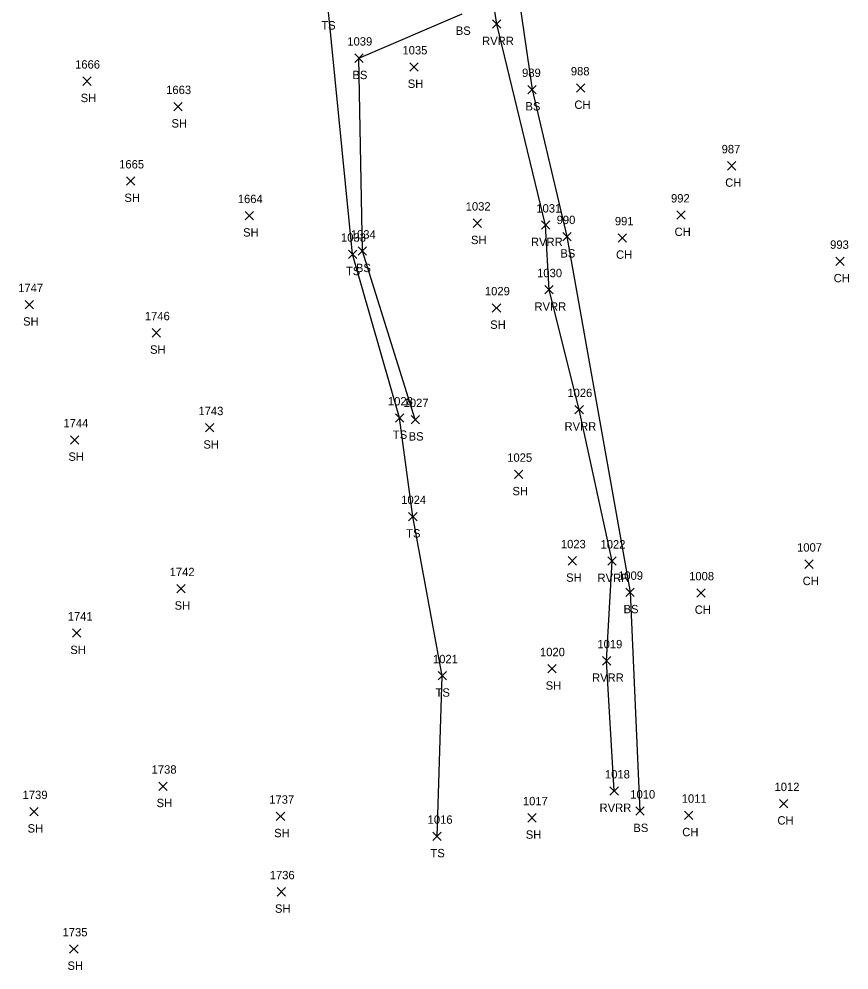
# Model space of a CAD drawing. Extents: x 1885914 to 1887218, y 756253 to 760620.
# Drawn here: x 1886537.5 to 1886735.6, y 759347 to 759574 of the extents above; entities that cross this region are included whole.
import ezdxf

# ---------------------------------------------------------------- set-up
doc = ezdxf.new("R2010")
doc.units = 0
for name, color, linetype in [('L_A', 7, 'Continuous'), ('L_I', 7, 'Continuous'), ('L_TIC', 7, 'Continuous'), ('LAWE', 7, 'Continuous'), ('LELB', 7, 'Continuous')]:
    doc.layers.add(name, color=color, linetype=linetype)

msp = doc.modelspace()

# ---------------------------------------------------------------- linework, layer by layer
at = {"layer": 'L_TIC'}
for points in [[(1886650.51, 759571.8), (1886652.51, 759573.8)], [(1886652.51, 759571.8), (1886650.51, 759573.8)], [(1886617.63, 759563.67), (1886619.63, 759565.67)], [(1886619.63, 759563.67), (1886617.63, 759565.67)], [(1886630.79, 759561.57), (1886632.79, 759563.57)], [(1886632.79, 759561.57), (1886630.79, 759563.57)], [(1886552.71, 759558.18), (1886554.71, 759560.18)], [(1886554.71, 759558.18), (1886552.71, 759560.18)], [(1886658.93, 759556.18), (1886660.93, 759558.18)], [(1886660.93, 759556.18), (1886658.93, 759558.18)], [(1886670.56, 759556.56), (1886672.56, 759558.56)], [(1886672.56, 759556.56), (1886670.56, 759558.56)], [(1886574.4, 759552.1), (1886576.4, 759554.1)], [(1886576.4, 759552.1), (1886574.4, 759554.1)], [(1886706.56, 759537.97), (1886708.56, 759539.97)], [(1886708.56, 759537.97), (1886706.56, 759539.97)], [(1886563.16, 759534.34), (1886565.16, 759536.34)], [(1886565.16, 759534.34), (1886563.16, 759536.34)], [(1886591.49, 759526.07), (1886593.49, 759528.07)], [(1886593.49, 759526.07), (1886591.49, 759528.07)], [(1886694.48, 759526.22), (1886696.48, 759528.22)], [(1886696.48, 759526.22), (1886694.48, 759528.22)], [(1886645.87, 759524.28), (1886647.87, 759526.28)], [(1886647.87, 759524.28), (1886645.87, 759526.28)], [(1886662.16, 759523.82), (1886664.16, 759525.82)], [(1886664.16, 759523.82), (1886662.16, 759525.82)], [(1886667.26, 759521.06), (1886669.26, 759523.06)], [(1886669.26, 759521.06), (1886667.26, 759523.06)], [(1886680.51, 759520.77), (1886682.51, 759522.77)], [(1886682.51, 759520.77), (1886680.51, 759522.77)], [(1886616.11, 759516.86), (1886618.11, 759518.86)], [(1886618.11, 759516.86), (1886616.11, 759518.86)], [(1886618.46, 759517.6), (1886620.46, 759519.6)], [(1886620.46, 759517.6), (1886618.46, 759519.6)], [(1886732.46, 759515.16), (1886734.46, 759517.16)], [(1886734.46, 759515.16), (1886732.46, 759517.16)], [(1886663, 759508.38), (1886665, 759510.38)], [(1886665, 759508.38), (1886663, 759510.38)], [(1886538.98, 759504.82), (1886540.98, 759506.82)], [(1886540.98, 759504.82), (1886538.98, 759506.82)], [(1886650.46, 759504.05), (1886652.46, 759506.05)], [(1886652.46, 759504.05), (1886650.46, 759506.05)], [(1886569.27, 759498.1), (1886571.27, 759500.1)], [(1886571.27, 759498.1), (1886569.27, 759500.1)], [(1886627.32, 759477.77), (1886629.32, 759479.77)], [(1886629.32, 759477.77), (1886627.32, 759479.77)], [(1886670.19, 759479.76), (1886672.19, 759481.76)], [(1886672.19, 759479.76), (1886670.19, 759481.76)], [(1886631.05, 759477.37), (1886633.05, 759479.37)], [(1886633.05, 759477.37), (1886631.05, 759479.37)], [(1886582, 759475.44), (1886584, 759477.44)], [(1886584, 759475.44), (1886582, 759477.44)], [(1886549.78, 759472.54), (1886551.78, 759474.54)], [(1886551.78, 759472.54), (1886549.78, 759474.54)], [(1886655.78, 759464.31), (1886657.78, 759466.31)], [(1886657.78, 759464.31), (1886655.78, 759466.31)], [(1886630.48, 759454.22), (1886632.48, 759456.22)], [(1886632.48, 759454.22), (1886630.48, 759456.22)], [(1886668.59, 759443.66), (1886670.59, 759445.66)], [(1886670.59, 759443.66), (1886668.59, 759445.66)], [(1886678.05, 759443.6), (1886680.05, 759445.6)], [(1886680.05, 759443.6), (1886678.05, 759445.6)], [(1886725.05, 759442.86), (1886727.05, 759444.86)], [(1886727.05, 759442.86), (1886725.05, 759444.86)], [(1886575.13, 759437), (1886577.13, 759439)], [(1886577.13, 759437), (1886575.13, 759439)], [(1886682.34, 759436.14), (1886684.34, 759438.14)], [(1886684.34, 759436.14), (1886682.34, 759438.14)], [(1886699.3, 759436), (1886701.3, 759438)], [(1886701.3, 759436), (1886699.3, 759438)], [(1886550.23, 759426.41), (1886552.23, 759428.41)], [(1886552.23, 759426.41), (1886550.23, 759428.41)], [(1886676.75, 759419.78), (1886678.75, 759421.78)], [(1886678.75, 759419.78), (1886676.75, 759421.78)], [(1886663.7, 759417.89), (1886665.7, 759419.89)], [(1886665.7, 759417.89), (1886663.7, 759419.89)], [(1886637.5, 759416.22), (1886639.5, 759418.22)], [(1886639.5, 759416.22), (1886637.5, 759418.22)], [(1886570.83, 759389.85), (1886572.83, 759391.85)], [(1886572.83, 759389.85), (1886570.83, 759391.85)], [(1886678.54, 759388.71), (1886680.54, 759390.71)], [(1886680.54, 759388.71), (1886678.54, 759390.71)], [(1886719.02, 759385.69), (1886721.02, 759387.69)], [(1886721.02, 759385.69), (1886719.02, 759387.69)], [(1886540.04, 759383.78), (1886542.04, 759385.78)], [(1886542.04, 759383.78), (1886540.04, 759385.78)], [(1886598.9, 759382.67), (1886600.9, 759384.67)], [(1886600.9, 759382.67), (1886598.9, 759384.67)], [(1886684.68, 759383.91), (1886686.68, 759385.91)], [(1886686.68, 759383.91), (1886684.68, 759385.91)], [(1886696.3, 759382.9), (1886698.3, 759384.9)], [(1886698.3, 759382.9), (1886696.3, 759384.9)], [(1886658.95, 759382.3), (1886660.95, 759384.3)], [(1886660.95, 759382.3), (1886658.95, 759384.3)], [(1886636.28, 759377.88), (1886638.28, 759379.88)], [(1886638.28, 759377.88), (1886636.28, 759379.88)], [(1886599.08, 759364.63), (1886601.08, 759366.63)], [(1886601.08, 759364.63), (1886599.08, 759366.63)], [(1886549.57, 759351), (1886551.57, 759353)], [(1886551.57, 759351), (1886549.57, 759353)]]:
    msp.add_lwpolyline(points, dxfattribs=at)
at = {"layer": 'LAWE'}
msp.add_lwpolyline([(1886679.54, 759389.71), (1886677.75, 759420.78), (1886679.05, 759444.6), (1886671.19, 759480.76), (1886664, 759509.38), (1886663.16, 759524.82), (1886651.51, 759572.8), (1886647.18, 759601.26), (1886641.69, 759620.32)], dxfattribs=at)
at = {"layer": 'LELB'}
for points in [[(1886651.59, 759963.58), (1886647.85, 759929.2), (1886639.89, 759913.67), (1886633.14, 759883.1), (1886633.96, 759851.09), (1886632.16, 759822.61), (1886631.66, 759800.6), (1886631.69, 759739.71), (1886631.53, 759709.44), (1886635.98, 759687.07), (1886641.47, 759657.6), (1886645.02, 759644.27), (1886643.52, 759637.8), (1886640.86, 759635.28), (1886641.28, 759631.71), (1886642.18, 759628.94), (1886648.32, 759617.92), (1886654.14, 759597.23), (1886659.93, 759557.18), (1886668.26, 759522.06), (1886683.34, 759437.14), (1886685.68, 759384.91)], [(1886637.28, 759378.88), (1886638.5, 759417.22), (1886631.48, 759455.22), (1886628.32, 759478.77), (1886617.11, 759517.86), (1886611.24, 759576.51), (1886639.28, 759593.88)], [(1886632.05, 759478.37), (1886619.46, 759518.6), (1886618.63, 759564.67), (1886643.3, 759575.24)]]:
    msp.add_lwpolyline(points, dxfattribs=at)

# ---------------------------------------------------------------- texts
at = {"layer": 'L_A'}
for s, p in [('TS', (1886609.65, 759571.51)), ('TS', (1886609.65, 759571.51)), ('BS', (1886641.74, 759570.24)), ('RVRR', (1886648.02, 759567.8)), ('BS', (1886617.07, 759559.67)), ('SH', (1886630.27, 759557.57)), ('SH', (1886552.2, 759554.18)), ('BS', (1886658.37, 759552.18)), ('CH', (1886670.05, 759552.56)), ('SH', (1886573.88, 759548.1)), ('CH', (1886706.05, 759533.97)), ('SH', (1886562.65, 759530.34)), ('SH', (1886590.97, 759522.07)), ('CH', (1886693.96, 759522.22)), ('SH', (1886645.36, 759520.28)), ('RVRR', (1886659.68, 759519.82)), ('BS', (1886666.7, 759517.06)), ('CH', (1886679.99, 759516.77)), ('TS', (1886615.52, 759512.86)), ('BS', (1886617.9, 759513.6)), ('CH', (1886731.94, 759511.16)), ('RVRR', (1886660.52, 759504.38)), ('SH', (1886538.46, 759500.82)), ('SH', (1886649.95, 759500.05)), ('SH', (1886568.76, 759494.1)), ('RVRR', (1886667.7, 759475.76)), ('TS', (1886626.72, 759473.77)), ('BS', (1886630.49, 759473.37)), ('SH', (1886581.49, 759471.44)), ('SH', (1886549.27, 759468.54)), ('SH', (1886655.27, 759460.31)), ('TS', (1886629.89, 759450.22)), ('SH', (1886668.08, 759439.66)), ('RVRR', (1886675.57, 759439.6)), ('CH', (1886724.53, 759438.86)), ('SH', (1886574.62, 759433)), ('BS', (1886681.78, 759432.14)), ('CH', (1886698.78, 759432)), ('SH', (1886549.72, 759422.41)), ('RVRR', (1886674.26, 759415.78)), ('TS', (1886636.91, 759412.22)), ('SH', (1886663.18, 759413.89)), ('SH', (1886570.32, 759385.85)), ('RVRR', (1886676.06, 759384.71)), ('CH', (1886718.51, 759381.69)), ('SH', (1886539.53, 759379.78)), ('SH', (1886598.39, 759378.67)), ('SH', (1886658.44, 759378.3)), ('BS', (1886684.12, 759379.91)), ('CH', (1886695.79, 759378.9)), ('TS', (1886635.69, 759373.88)), ('SH', (1886598.57, 759360.63)), ('SH', (1886549.06, 759347))]:
    msp.add_text(s, height=2, dxfattribs=at).set_placement(p)
at = {"layer": 'L_I'}
for s, p in [('1039', (1886615.85, 759567.67)), ('1035', (1886629.01, 759565.57)), ('1666', (1886550.87, 759562.18)), ('989', (1886657.56, 759560.18)), ('988', (1886669.2, 759560.56)), ('1663', (1886572.61, 759556.1)), ('987', (1886705.19, 759541.97)), ('1665', (1886561.38, 759538.34)), ('1664', (1886589.7, 759530.07)), ('992', (1886693.11, 759530.22)), ('1032', (1886644.1, 759528.28)), ('1031', (1886660.96, 759527.82)), ('990', (1886665.81, 759525.06)), ('991', (1886679.71, 759524.77)), ('1033', (1886614.34, 759520.86)), ('1034', (1886616.69, 759521.6)), ('993', (1886731.09, 759519.16)), ('1030', (1886661.15, 759512.38)), ('1747', (1886537.28, 759508.82)), ('1029', (1886648.68, 759508.05)), ('1746', (1886567.52, 759502.1)), ('1026', (1886668.37, 759483.76)), ('1028', (1886625.54, 759481.77)), ('1027', (1886629.28, 759481.37)), ('1743', (1886580.31, 759479.44)), ('1744', (1886548.09, 759476.54)), ('1025', (1886654.01, 759468.31)), ('1024', (1886628.71, 759458.22)), ('1023', (1886666.82, 759447.66)), ('1022', (1886676.28, 759447.6)), ('1007', (1886723.2, 759446.86)), ('1742', (1886573.44, 759441)), ('1009', (1886680.48, 759440.14)), ('1008', (1886697.44, 759440)), ('1741', (1886549.11, 759430.41)), ('1019', (1886675.54, 759423.78)), ('1020', (1886661.84, 759421.89)), ('1021', (1886636.29, 759420.22)), ('1738', (1886569.14, 759393.85)), ('1018', (1886677.34, 759392.71)), ('1012', (1886717.82, 759389.69)), ('1739', (1886538.34, 759387.78)), ('1010', (1886683.39, 759387.91)), ('1011', (1886695.67, 759386.9)), ('1737', (1886597.21, 759386.67)), ('1017', (1886657.75, 759386.3)), ('1016', (1886635.02, 759381.88)), ('1736', (1886597.33, 759368.63)), ('1735', (1886547.88, 759355))]:
    msp.add_text(s, height=2, dxfattribs=at).set_placement(p)

doc.saveas('drawing.dxf')
